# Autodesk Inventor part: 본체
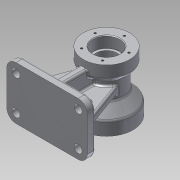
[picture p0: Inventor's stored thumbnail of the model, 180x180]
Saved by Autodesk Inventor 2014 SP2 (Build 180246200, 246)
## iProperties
Created: 2015-08
Part Number: 본체
Material: 알루미늄 6061
Document SubType Name: Modeling
Designer: 201-19
Density: 2.71 g/cm^3
Appearance: 알루미늄 - 평지
Mass: 1057.76 g
Surface Area: 749.472 cm^2
Volume: 390.316 cm^3
Author: 201-19
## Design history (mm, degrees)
sketch "스케치2"
  geometry: L1 (-61, 40)-(61, 40); L2 (61, 40)-(61, -40); L3 (61, -40)-(-61, -40); L4 (-61, -40)-(-61, 40); L5 (-61, 40)-(61, -40); L6 (61, 40)-(-61, -40); 1 further point
  constraints: 12 end point, 2 midpoint, 2 parallel, 1 horizontal, 1 perpendicular
  dimensions: "d0" = 122 distance of L1.start L1.end; "d1" = 80 distance of L1.end L2.end
extrude "돌출1" new body sketch "스케치2" distance "d2" = 12; taper "d3" = 0 deg
node "작업 평면1"
sketch "스케치4"
  geometry: L1 (0, 44.419)-(0, -44.419); L2 (61, 40)-(-61, 40) reference; L3 (0, 40)-(35, 40); L4 (35, 40)-(35, 20); L5 (35, 20)-(26, 14.804); L6 (26, 14.804)-(26, -13.315); L7 (26, -13.315)-(40, -30); L8 (40, -30)-(40, -50); L9 (40, -50)-(0, -50); L10 (0, -50)-(0, 40); 2 further points
  constraints: 18 end point, 3 parallel, 2 collinear, 2 midpoint, 1 coincident, 1 perpendicular, 1 vertical
  dimensions: "d13" = 90 distance between parallel lines of L9 L3; "d14" = 70 diameter of L4 L1; "d15" = 60 deg angle of L6 L5; "d16" = 20 distance of L3.end L4.end; "d17" = 20 distance of L7.end L8.end; "d18" = 40 deg angle of L6 L7; "d19" = 80 diameter of L8 L1; "d20" = 52 diameter of L6 L1
revolve "회전1" sketch "스케치4" stored, may be unused: angle "d21" = 90 deg
sketch "스케치10"
  geometry: L1 (-6, 6)-(6, 6); L2 (6, 6)-(6, -6); L3 (6, -6)-(-6, -6); L4 (-6, -6)-(-6, 6); L5 (-6, 6)-(6, -6); L6 (6, 6)-(-6, -6); 1 further point
  constraints: 12 end point, 2 midpoint, 2 parallel, 1 horizontal, 1 perpendicular
  dimensions: "d40" = 12 distance of L1.start L1.end; "d41" = 12 distance of L1.end L2.end
extrude "돌출2" join sketch "스케치10" stored distance "d42" = 12; taper "d43" = 0 deg
sketch "스케치11"
  geometry: L1 (61, 12)-(-61, 12) reference; L2 (-25.091, 83.185)-(-51, 12); 2 further points
  constraints: 2 end point, 1 point on line, 2 other
  dimensions: "d44" = 10 distance of L1.end L2.end; "d45" = 70 deg angle of L1 L2
feature "리브1" sketch "스케치11" dims "d46" = 1, "d47" = 12, "d48" = 0, "d49" = 0, "d50" = 1, "d51" = 1
sketch "스케치15"
  geometry: L1 (-61, -40)-(-61, 40) reference; L2 (-61, 40)-(61, 40) reference; L3 (61, 40)-(61, -40) reference; L4 (61, -40)-(-61, -40) reference; L5 (-6, -30)-(6, -30); L6 (6, -30)-(6, -6); L7 (6, -6)-(-6, -6); L8 (-6, -6)-(-6, -30); L9 (-6, -30)-(6, -6); L10 (6, -30)-(-6, -6); L11 (-61, 0)-(61, 0); L12 (-6, 30)-(6, 30); L13 (6, 30)-(6, 6); L14 (6, 6)-(-6, 6); L15 (-6, 6)-(-6, 30); L16 (-6, 30)-(6, 6); L17 (6, 30)-(-6, 6); 5 further points
  constraints: 26 end point, 7 midpoint, 6 symmetric about line, 2 parallel, 1 horizontal, 1 perpendicular, 1 vertical alignment
  dimensions: "d57" = 6 distance from line of point (0, 0) L7; "d58" = 10 distance between parallel lines of L4 L5; "d59" = 12 distance of L5.start L5.end
extrude "돌출3" join sketch "스케치15" stored distance "d60" = 12; taper "d61" = 0 deg
feature "면 기울기1" dims angle "d62" = 10 deg
hole "구멍1" diameter "d65" = 52; stored, may be unused: countersink angle "d69" = 90 deg, drill point angle "d71" = 0 deg; dims "d63" = 10, "d64" = 10, "d66" = 6, "d67" = 4, "d68" = 2, "d70" = 20
hole "구멍2" diameter "d74" = 38; stored, may be unused: countersink angle "d78" = 90 deg, drill point angle "d80" = 0 deg; dims "d72" = 10, "d73" = 10, "d75" = 6, "d76" = 4, "d77" = 2, "d79" = 3
hole "구멍3" diameter "d83" = 32; stored, may be unused: countersink angle "d87" = 90 deg, drill point angle "d89" = 0 deg; dims "d84" = 6, "d85" = 4, "d86" = 2, "d88" = 32, "d99" = 10, "d100" = 10
hole "구멍4" diameter "d92" = 40; stored, may be unused: countersink angle "d96" = 90 deg, drill point angle "d98" = 0 deg; dims "d90" = 10, "d91" = 10, "d93" = 6, "d94" = 4, "d95" = 2, "d97" = 17
fillet "모깎기1" dims "d101" = 14
sketch "스케치16"
  geometry: L1 (-47, -26)-(47, -26); L2 (47, -26)-(47, 26); L3 (47, 26)-(-47, 26); L4 (-47, 26)-(-47, -26); L5 (-47, -26)-(47, 26); L6 (47, -26)-(-47, 26); 5 further points
  constraints: 12 end point, 4 coincident, 2 midpoint, 2 parallel, 1 horizontal, 1 perpendicular
  dimensions: "d102" = 94 distance of L2.end L3.end; "d103" = 52 distance of L1.end L2.end
hole "구멍5" sketch "스케치16" at (-47, 26), (47, 26), (47, -26), (-47, -26) diameter "d104" = 12; stored, may be unused: countersink angle "d108" = 90 deg, drill point angle "d110" = 0 deg; dims "d105" = 6, "d106" = 4, "d107" = 2, "d109" = 17
sketch "스케치17"
  geometry: L1 (27, 24)-(27, 18); L2 (21, 24)-(21, 18); L3 (33, 18)-(33, 24); L4 (98, -12)-(4, -12) reference; A1 r 6 centre (27, 24) between (33, 24) and (21, 24); A2 r 6 centre (27, 18) between (21, 18) and (33, 18); 2 further points
  constraints: 8 end point, 4 point on circle, 4 tangent, 2 centre point, 1 midpoint, 1 parallel, 1 vertical
  dimensions: "d111" = 12 distance between parallel lines of L3 L2; "d112" = 6 distance of L1.end L1.start; "d114" = 30 distance from line of L4 L1.end; "d115" = 24 horizontal distance of point (51, -12) point (27, 21)
extrude "돌출4" cut sketch "스케치17" stored distance "d116" = 12; taper "d117" = 0 deg
fillet "모깎기2" dims "d118" = 5
fillet "모깎기3" dims "d119" = 0.3
fillet "모깎기4" dims "d120" = 3
fillet "모깎기5" dims "d121" = 3
fillet "모깎기6" dims "d122" = 3
chamfer "모따기1" distance "d123" = 1; stored, may be unused: second distance "d124" = 2, angle "d125" = 45 deg
chamfer "모따기2" distance "d126" = 1; stored, may be unused: second distance "d127" = 2, angle "d128" = 45 deg
sketch "스케치18" dims "d129" = 66
  geometry: L1 (0, 40)-(0, -90); 7 further points
  constraints: 2 end point, 2 vertical alignment, 1 point on line, 1 vertical, 9 other
  dimensions: "d132" = 360 deg dimension on point (0, 0) point (0, 33) (derived)
hole "구멍6" sketch "스케치18" at (0, 33), (-31.385, 10.198), (-19.397, -26.698), (19.397, -26.698), (31.385, 10.198) diameter "d134" = 3.242; stored, may be unused: countersink angle "d138" = 90 deg, drill point angle "d140" = 118 deg; dims "d135" = 10, "d136" = 4, "d137" = 2, "d139" = 13
sketch "스케치19" dims "d141" = 54
  geometry: L1 (0, 35)-(0, -90); 7 further points
  constraints: 2 end point, 2 vertical alignment, 1 point on line, 1 vertical, 9 other
  dimensions: "d144" = 360 deg dimension on point (0, 0) point (0, 27) (derived)
hole "구멍7" sketch "스케치19" at (0, 27), (-25.679, 8.343), (-15.87, -21.843), (15.87, -21.843), (25.679, 8.343) diameter "d146" = 3.242; stored, may be unused: countersink angle "d150" = 90 deg, drill point angle "d152" = 118 deg; dims "d147" = 10, "d148" = 4, "d149" = 2, "d151" = 13
node "솔리드1"
mirror "대칭1"
mirror "대칭2"
node "투영된 루프2"
